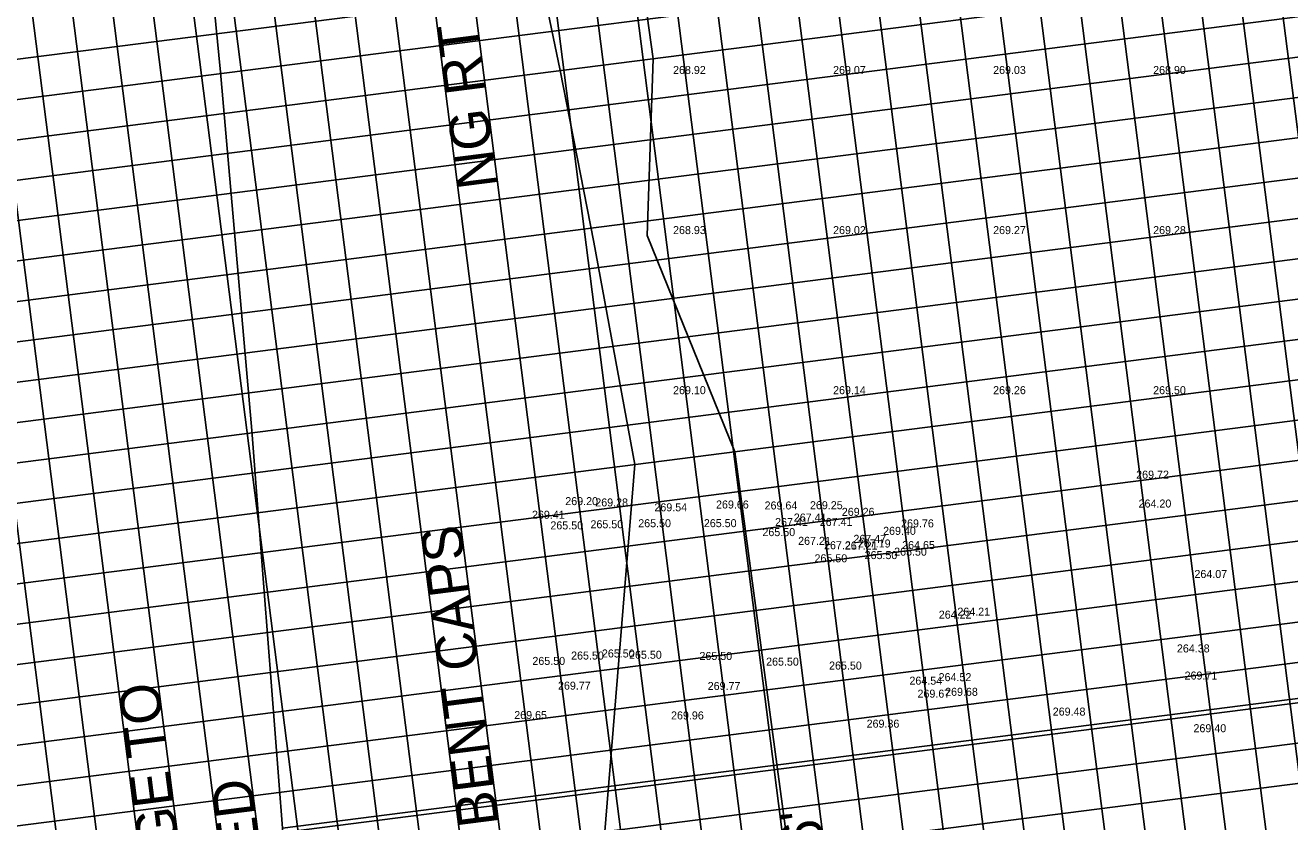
# Model space of a CAD drawing. Extents: x 2166991 to 2168450, y 842134 to 844444.
# Drawn here: x 2167712.5 to 2167870.5, y 843507.6 to 843607.1 of the extents above; entities that cross this region are included whole.
import ezdxf

# ---------------------------------------------------------------- set-up
doc = ezdxf.new("R2010")
doc.units = 0
for name, color, linetype in [('Exist Hydrographic Top of Bank', 7, 'Continuous'), ('Exist Plan Preparation Drainage Notes Label', 7, 'Continuous'), ('Prop Drainage Structure Drop Inlet Grate 2 Narrow Slots and Flat Grates 840 29 CELL', 7, 'Continuous'), ('Prop Erosion Rip Rap Class II', 7, 'Continuous'), ('Prop Plan Preparation Excavation Hatching', 7, 'Continuous'), ('Prop Plan Preparation Excavation Hatching Label', 7, 'Continuous'), ('Scratch_Level_1', 7, 'Continuous'), ('Scratch_Level_3', 7, 'Continuous')]:
    doc.layers.add(name, color=color, linetype=linetype)

msp = doc.modelspace()

# ---------------------------------------------------------------- linework, layer by layer
at = {"layer": 'Exist Plan Preparation Drainage Notes Label'}
for p, q in [((2167933.95, 842789.5), (2167775.57, 844029.42)), ((2167884.35, 842783.16), (2167725.98, 844023.09)), ((2167834.76, 842776.83), (2167676.38, 844016.75)), ((2167965.5, 842818.73), (2167813.46, 844009.06)), ((2167970.46, 842819.36), (2167818.42, 844009.69)), ((2167950.62, 842816.83), (2167798.58, 844007.16)), ((2167955.58, 842817.46), (2167803.54, 844007.79)), ((2167960.54, 842818.1), (2167808.5, 844008.43)), ((2167940.7, 842815.56), (2167788.66, 844005.89)), ((2167945.66, 842816.2), (2167793.62, 844006.52)), ((2167925.82, 842813.66), (2167773.78, 844003.99)), ((2167935.74, 842814.93), (2167783.7, 844005.26)), ((2167915.9, 842812.39), (2167763.86, 844002.72)), ((2167920.86, 842813.03), (2167768.82, 844003.36)), ((2167901.03, 842810.49), (2167748.98, 844000.82)), ((2167905.98, 842811.13), (2167753.94, 844001.46)), ((2167910.94, 842811.76), (2167758.9, 844002.09)), ((2167891.11, 842809.23), (2167739.06, 843999.56)), ((2167896.07, 842809.86), (2167744.02, 844000.19)), ((2167876.23, 842807.33), (2167724.19, 843997.66)), ((2167886.15, 842808.59), (2167734.11, 843998.92)), ((2167866.31, 842806.06), (2167714.27, 843996.39)), ((2167871.27, 842806.69), (2167719.23, 843997.02)), ((2167851.43, 842804.16), (2167699.39, 843994.49)), ((2167856.39, 842804.79), (2167704.35, 843995.12)), ((2167861.35, 842805.43), (2167709.31, 843995.76)), ((2167841.51, 842802.89), (2167689.47, 843993.22)), ((2167846.47, 842803.53), (2167694.43, 843993.85)), ((2167826.63, 842800.99), (2167674.59, 843991.32)), ((2167836.55, 842802.26), (2167684.51, 843992.59)), ((2167816.71, 842799.72), (2167664.67, 843990.05)), ((2167821.67, 842800.36), (2167669.63, 843990.69)), ((2167806.79, 842798.46), (2167654.75, 843988.79)), ((2167811.75, 842799.09), (2167659.71, 843989.42)), ((2168125.74, 843655.78), (2167629.77, 843592.43)), ((2168126.37, 843650.82), (2167630.4, 843587.47)), ((2168127.01, 843645.86), (2167606.24, 843579.34)), ((2168127.64, 843640.9), (2167631.67, 843577.55)), ((2168128.27, 843635.94), (2167632.3, 843572.59)), ((2168128.91, 843630.98), (2167632.94, 843567.63)), ((2168129.54, 843626.02), (2167633.57, 843562.67)), ((2168130.17, 843621.06), (2167634.2, 843557.71)), ((2168130.81, 843616.1), (2167634.84, 843552.75)), ((2168131.44, 843611.14), (2167635.47, 843547.79)), ((2168132.07, 843606.18), (2167636.1, 843542.83)), ((2168132.71, 843601.22), (2167636.74, 843537.87)), ((2168133.34, 843596.26), (2167612.57, 843529.74)), ((2168133.97, 843591.3), (2167638, 843527.95)), ((2168134.61, 843586.34), (2167638.64, 843522.99)), ((2168135.24, 843581.38), (2167639.27, 843518.03)), ((2168135.87, 843576.42), (2167639.9, 843513.07)), ((2168136.51, 843571.46), (2167640.54, 843508.11)), ((2168137.14, 843566.5), (2167641.17, 843503.15)), ((2168137.77, 843561.54), (2167641.8, 843498.19)), ((2168138.41, 843556.58), (2167642.44, 843493.23)), ((2168139.04, 843551.62), (2167643.07, 843488.27)), ((2168139.68, 843546.66), (2167618.91, 843480.15))]:
    msp.add_line(p, q, dxfattribs=at)
at = {"layer": 'Prop Drainage Structure Drop Inlet Grate 2 Narrow Slots and Flat Grates 840 29 CELL'}
msp.add_lwpolyline([(2167811.3, 843414.12), (2167807.83, 843456.76), (2167807.84, 843504.28), (2167801.18, 843553.83), (2167790.23, 843580.86), (2167790.98, 843602.94), (2167784.08, 843652.46), (2167781.01, 843702.48), (2167748.47, 843748.73), (2167729.16, 843847.07), (2167716.86, 843895.91), (2167712.99, 843945.82), (2167712.65, 843970.98), (2167709.18, 843995.74)], dxfattribs=at)
at = {"layer": 'Prop Plan Preparation Excavation Hatching'}
msp.add_lwpolyline([(2167780.31, 843466.62), (2167784.52, 843501.3), (2167788.71, 843552.24), (2167783.57, 843580.01), (2167779.35, 843601.45), (2167769.15, 843650.56), (2167754.8, 843699.13), (2167753.25, 843749.34), (2167741.46, 843798.24), (2167722.31, 843846.2), (2167712.49, 843895.35), (2167692.49, 843943.2), (2167687.3, 843967.74), (2167682.51, 843992.33)], dxfattribs=at)
at = {"layer": 'Prop Plan Preparation Excavation Hatching Label'}
msp.add_lwpolyline([(2167698.15, 843912.6), (2167700.9, 843897.02), (2167704.98, 843873.76), (2167712.78, 843830.82), (2167715.25, 843815.08), (2167719.44, 843788.58), (2167721.24, 843770.88), (2167724.14, 843742.72), (2167725.44, 843727.75), (2167727.98, 843698.45), (2167729.76, 843678.17), (2167732.36, 843648.31), (2167734.01, 843631.06), (2167736.91, 843601.24), (2167740.82, 843556.48), (2167742.38, 843536.39), (2167744.64, 843506.82), (2167745.73, 843489.59), (2167747.12, 843463.2)], dxfattribs=at)
at = {"layer": 'Scratch_Level_1'}
for p, q in [((2168101.65, 843552.42), (2167744.64, 843506.82)), ((2167742.39, 843536.24), (2167742.38, 843536.39))]:
    msp.add_line(p, q, dxfattribs=at)

# ---------------------------------------------------------------- texts
at = {"layer": 'Exist Hydrographic Top of Bank'}
msp.add_text('2\'-6" END BENT CAPS', height=5, rotation=97.279, dxfattribs=at).set_placement((2167775.63, 843476.4))
at = {"layer": 'Prop Erosion Rip Rap Class II'}
for s, p in [('NG RT', (2167771.51, 843587)), ('EXIST BRIDGE TO', (2167736.43, 843467.74)), ('BE REMOVED', (2167746.35, 843469.01)), ("WSEL = 264.6'", (2167817.32, 843465.21))]:
    msp.add_text(s, height=5, rotation=97.279, dxfattribs=at).set_placement(p)
at = {"layer": 'Scratch_Level_3'}
for s, p in [('268.92', (2167793.47, 843601.03)), ('269.07', (2167813.47, 843601.03)), ('269.03', (2167833.47, 843601.03)), ('268.90', (2167853.47, 843601.03)), ('268.93', (2167793.47, 843581.03)), ('269.02', (2167813.47, 843581.03)), ('269.27', (2167833.47, 843581.03)), ('269.28', (2167853.47, 843581.03)), ('269.10', (2167793.47, 843561.03)), ('269.14', (2167813.47, 843561.03)), ('269.26', (2167833.47, 843561.03)), ('269.50', (2167853.47, 843561.03)), ('269.72', (2167851.35, 843550.48)), ('269.20', (2167780, 843547.17)), ('269.28', (2167783.75, 843547.01)), ('269.54', (2167791.14, 843546.4)), ('269.66', (2167798.84, 843546.75)), ('269.64', (2167804.91, 843546.63)), ('269.25', (2167810.58, 843546.66)), ('264.20', (2167851.65, 843546.87)), ('269.41', (2167775.84, 843545.47)), ('267.41', (2167808.56, 843545.12)), ('269.26', (2167814.56, 843545.83)), ('265.50', (2167778.14, 843544.14)), ('265.50', (2167783.15, 843544.28)), ('265.50', (2167789.12, 843544.41)), ('265.50', (2167797.32, 843544.42)), ('265.50', (2167804.64, 843543.3)), ('267.41', (2167806.22, 843544.56)), ('267.41', (2167811.8, 843544.57)), ('269.40', (2167819.72, 843543.46)), ('269.76', (2167821.97, 843544.39)), ('267.21', (2167809.1, 843542.21)), ('267.21', (2167812.34, 843541.66)), ('267.21', (2167814.94, 843541.61)), ('267.47', (2167816.01, 843542.46)), ('267.19', (2167816.57, 843541.88)), ('264.65', (2167822.1, 843541.68)), ('265.50', (2167811.15, 843540.03)), ('265.50', (2167817.41, 843540.43)), ('265.50', (2167821.1, 843540.86)), ('264.07', (2167858.63, 843538.07)), ('264.22', (2167826.68, 843532.99)), ('264.21', (2167829, 843533.36)), ('265.50', (2167780.73, 843527.88)), ('265.50', (2167784.58, 843528.14)), ('265.50', (2167787.97, 843527.98)), ('265.50', (2167796.77, 843527.83)), ('264.38', (2167856.44, 843528.77)), ('265.50', (2167775.89, 843527.21)), ('265.50', (2167805.1, 843527.12)), ('265.50', (2167812.97, 843526.63)), ('269.77', (2167779.09, 843524.12)), ('264.54', (2167823.01, 843524.74)), ('264.52', (2167826.66, 843525.18)), ('269.71', (2167857.4, 843525.38)), ('269.77', (2167797.8, 843524.08)), ('269.67', (2167824.02, 843523.12)), ('269.68', (2167827.47, 843523.35)), ('269.65', (2167773.62, 843520.45)), ('269.96', (2167793.22, 843520.4)), ('269.36', (2167817.66, 843519.37)), ('269.48', (2167840.92, 843520.88)), ('269.40', (2167858.51, 843518.8))]:
    msp.add_text(s, height=1, dxfattribs=at).set_placement(p)

doc.saveas('drawing.dxf')
